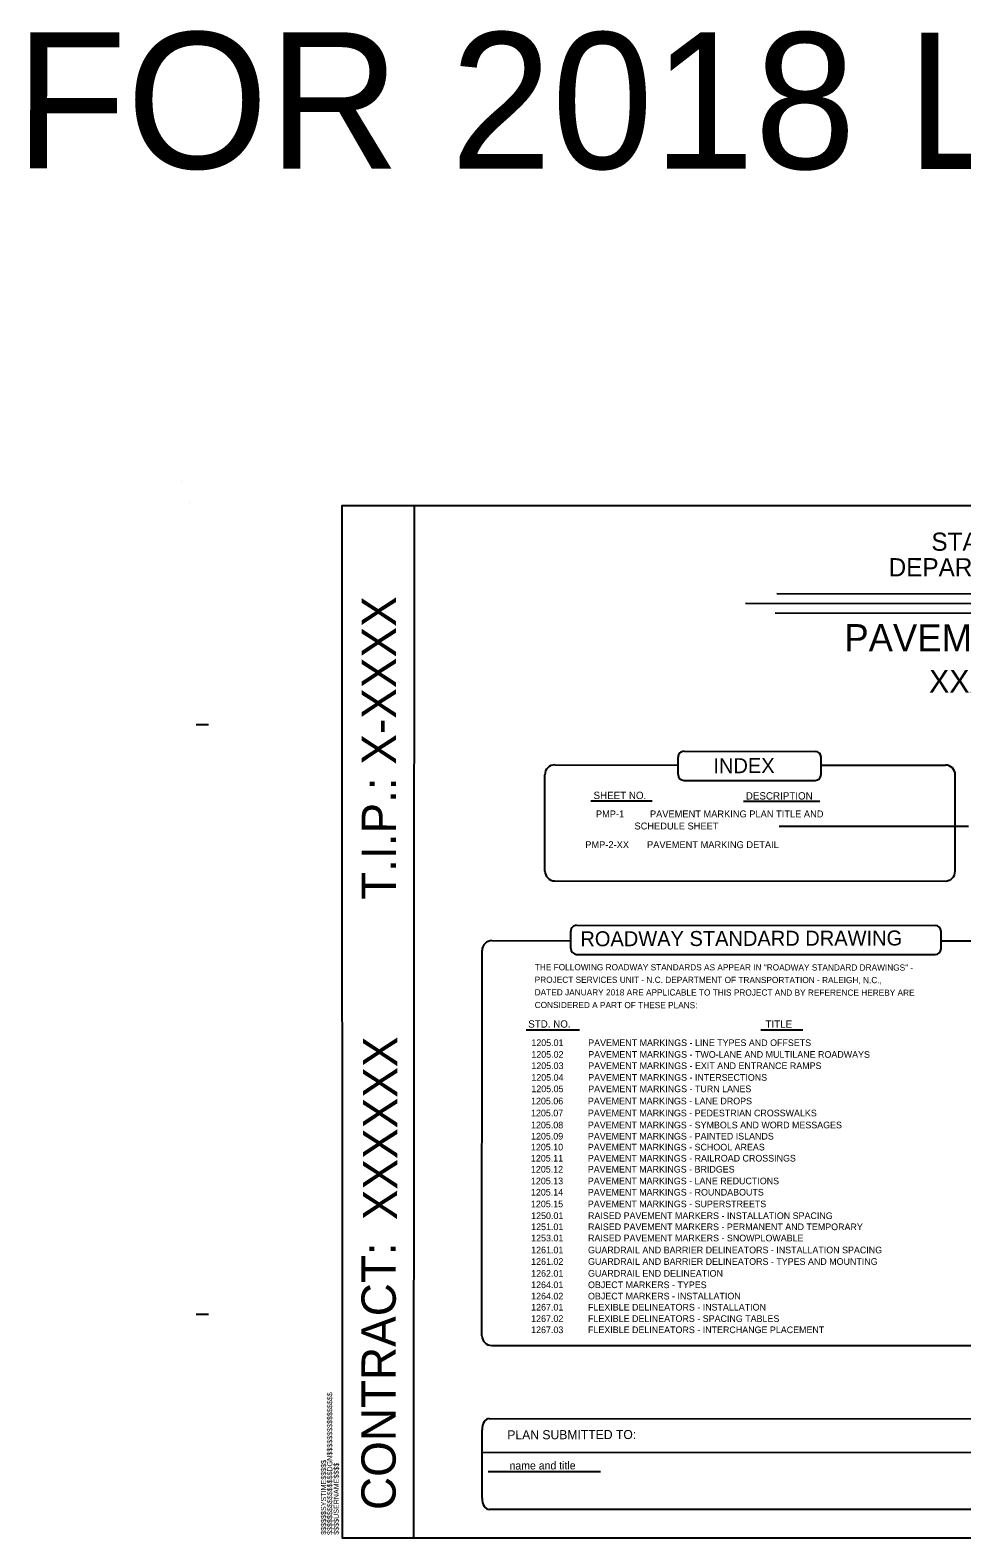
# Model space of a CAD drawing. Extents: x 2412958 to 2415566, y 564352 to 569392.
# Drawn here: x 2412958 to 2413907, y 567858 to 569392 of the extents above; entities that cross this region are included whole.
import ezdxf

# ---------------------------------------------------------------- set-up
doc = ezdxf.new("R2010")
doc.units = 0
for name, color, linetype in [('Default', 7, 'Continuous'), ('DEV BORDER CELL', 7, 'Continuous'), ('DEV TITLE SHEET CELL', 7, 'Continuous'), ('Old_Level_41', 7, 'Continuous'), ('Sheet Title CELL', 7, 'Continuous')]:
    doc.layers.add(name, color=color, linetype=linetype)

msp = doc.modelspace()

# ---------------------------------------------------------------- linework, layer by layer
at = {"layer": 'Default'}
for p, q in [((2413720.6, 568581.9), (2413913.3, 568581.9)), ((2413425.3, 567979.1), (2414032.2, 567979.2)), ((2413418.1, 567898.3), (2413418.1, 567967.7)), ((2413418.1, 567944.8), (2413939.2, 567945)), ((2413424.5, 567925.4), (2413538.6, 567925.3)), ((2414032.3, 567886.9), (2413425.3, 567886.8))]:
    msp.add_line(p, q, dxfattribs=at)
for points in [[(2413718.3, 568818.8), (2414412.1, 568818.4)], [(2413686.3, 568809), (2414440.8, 568808.7)], [(2413716.6, 568799.3), (2414410.4, 568798.9)]]:
    msp.add_lwpolyline(points, dxfattribs=at)
for centre, major_axis, start_param, end_param in [((2413425.3, 567967.7), (0, 11.5), 0.000702, 1.571498), ((2413425.3, 567898.3), (0, -11.5), 4.713091, 6.283887)]:
    msp.add_ellipse(centre, major_axis=major_axis, ratio=0.62659, start_param=start_param, end_param=end_param, dxfattribs=at)
at = {"layer": 'DEV BORDER CELL'}
for p, q in [((2413112.6, 568933), (2413112.6, 568933)), ((2413120, 568911.9), (2413120, 568911.9))]:
    msp.add_line(p, q, dxfattribs=at)
at = {"layer": 'Old_Level_41'}
for p, q in [((2413127, 568685.4), (2413139.5, 568685.4)), ((2413127, 568085.4), (2413139.5, 568085.4))]:
    msp.add_line(p, q, dxfattribs=at)
at = {"layer": 'Sheet Title CELL'}
for p, q in [((2413617.7, 568634.6), (2413617.7, 568652.3)), ((2413763.2, 568634.6), (2413763.2, 568652.2)), ((2413482.1, 568536.4), (2413482.1, 568634.4)), ((2413492.1, 568644.4), (2413617.7, 568644.3)), ((2413763.2, 568644.2), (2413889.8, 568644.2)), ((2413899.7, 568536.2), (2413899.8, 568634.2)), ((2413528.8, 568608), (2413591.4, 568608)), ((2413684.4, 568607.4), (2413762.1, 568607.4)), ((2413492.1, 568526.4), (2413889.7, 568526.2)), ((2413428.2, 568465.6), (2413508.4, 568465.5)), ((2413508.4, 568457.6), (2413508.4, 568475.2)), ((2413885.3, 568457.4), (2413885.3, 568475)), ((2413885.3, 568465.4), (2413961.1, 568465.3)), ((2413418, 568063.6), (2413418.2, 568455.6)), ((2413463, 568374.9), (2413517.2, 568374.9)), ((2413702, 568374.9), (2413744.8, 568374.9)), ((2413428, 568053.6), (2413960.9, 568053.6))]:
    msp.add_line(p, q, dxfattribs=at)
msp.add_lwpolyline([(2414775.5, 568908), (2413275.5, 568907.9), (2413275.6, 567857.9), (2414775.6, 567858)], close=True, dxfattribs=at)
for points in [[(2413348.7, 567857.9), (2413349.2, 568907.9)], [(2413623.7, 568658.3), (2413757.2, 568658.2)], [(2413623.7, 568628.6), (2413757.2, 568628.6)], [(2413514.4, 568481.2), (2413879.3, 568481)], [(2413514.4, 568451.6), (2413879.3, 568451.4)]]:
    msp.add_lwpolyline(points, dxfattribs=at)
for centre, radius, start, end in [((2413623.7, 568652.3), 6, 89.9734, 179.9734), ((2413757.2, 568652.2), 6, 359.9734, 89.9734), ((2413492.1, 568634.4), 10, 89.9734, 179.9734), ((2413623.7, 568634.6), 6, 179.9734, 269.9734), ((2413757.2, 568634.6), 6, 269.9734, 359.9734), ((2413889.8, 568634.2), 10, 359.9734, 89.9734), ((2413492.1, 568536.4), 10, 179.9734, 269.9734), ((2413889.7, 568536.2), 10, 269.9734, 359.9734), ((2413514.4, 568475.2), 6, 89.9734, 179.9734), ((2413879.3, 568475), 6, 359.9734, 89.9734), ((2413428.2, 568455.6), 10, 89.9734, 179.9734), ((2413514.4, 568457.6), 6, 179.9734, 269.9734), ((2413879.3, 568457.4), 6, 269.9734, 359.9734), ((2413428, 568063.6), 10, 179.9734, 269.9734)]:
    msp.add_arc(centre, radius, start, end, dxfattribs=at)

# ---------------------------------------------------------------- texts
at = {"layer": 'Default'}
for s, height, rotation, p in [('FOR 2018 LET PROJECTS', 138.702, 359.9734, (2412942.9, 569251.3)), ('STATE OF NORTH CAROLINA', 18.494, 359.9734, (2413875.5, 568862.3)), ('DEPARTMENT OF TRANSPORTATION', 18.494, 359.9734, (2413832, 568836.3)), ('T.I.P.: X-XXXX', 34.925, 89.9734, (2413330.5, 568507.1)), ('PAVEMENT MARKING PLAN', 27.74, 359.9734, (2413786.9, 568759.9)), ('XXXXXXXXXX COUNTY', 23.116, 359.9734, (2413873.1, 568718)), ('INDEX', 15.26, 0.1557, (2413653.6, 568635.9)), ('SHEET NO.', 7.45, 359.9734, (2413531.6, 568609.7)), ('DESCRIPTION', 7.45, 359.9734, (2413686.6, 568609.2)), ('PMP-1          PAVEMENT MARKING PLAN TITLE AND', 7.053, 360, (2413534, 568591)), ('               SCHEDULE SHEET', 7.053, 360, (2413534, 568578.7)), ('   PMP-2-XX       PAVEMENT MARKING DETAIL', 7.053, 360, (2413515.3, 568559.7)), ('ROADWAY STANDARD DRAWING', 15.257, 0.1557, (2413518.2, 568459.8)), ('STD. NO.', 7.45, 359.9734, (2413465.1, 568377.1)), ('TITLE', 7.45, 359.9734, (2413706.7, 568377)), ('XXXXXX', 34.92, 89.9734, (2413331.7, 568181.1)), ('1205.01          PAVEMENT MARKINGS - LINE TYPES AND OFFSETS', 6.771, 360, (2413468.3, 568358.3)), ('1205.02          PAVEMENT MARKINGS - TWO-LANE AND MULTILANE ROADWAYS', 6.771, 360, (2413468.3, 568346.4)), ('1205.03          PAVEMENT MARKINGS - EXIT AND ENTRANCE RAMPS', 6.771, 360, (2413468.3, 568334.9)), ('1205.04          PAVEMENT MARKINGS - INTERSECTIONS', 6.771, 360, (2413468.3, 568323)), ('1205.05          PAVEMENT MARKINGS - TURN LANES', 6.771, 360, (2413468.3, 568311.4)), ('1205.06          PAVEMENT MARKINGS - LANE DROPS', 6.771, 360, (2413468, 568299)), ('1205.07          PAVEMENT MARKINGS - PEDESTRIAN CROSSWALKS', 6.771, 360, (2413468, 568286.8)), ('1205.08          PAVEMENT MARKINGS - SYMBOLS AND WORD MESSAGES', 6.771, 360, (2413468, 568274.6)), ('1205.09          PAVEMENT MARKINGS - PAINTED ISLANDS', 6.771, 360, (2413468, 568263.2)), ('1205.10          PAVEMENT MARKINGS - SCHOOL AREAS', 6.771, 360, (2413467.9, 568252.1)), ('1205.11          PAVEMENT MARKINGS - RAILROAD CROSSINGS', 6.771, 360, (2413467.9, 568240.8)), ('1205.12          PAVEMENT MARKINGS - BRIDGES', 6.771, 360, (2413467.9, 568229.6)), ('1205.13          PAVEMENT MARKINGS - LANE REDUCTIONS', 6.771, 360, (2413467.9, 568217.7)), ('1205.14          PAVEMENT MARKINGS - ROUNDABOUTS', 6.771, 360, (2413467.9, 568206.2)), ('1205.15          PAVEMENT MARKINGS - SUPERSTREETS', 6.771, 360, (2413467.9, 568194.3)), ('1250.01          RAISED PAVEMENT MARKERS - INSTALLATION SPACING', 6.771, 360, (2413468.1, 568182.3)), ('1251.01          RAISED PAVEMENT MARKERS - PERMANENT AND TEMPORARY', 6.771, 360, (2413468.1, 568171)), ('CONTRACT:', 34.92, 89.9734, (2413330.2, 567886.2)), ('1253.01          RAISED PAVEMENT MARKERS - SNOWPLOWABLE', 6.771, 360, (2413468.1, 568159.6)), ('1261.01          GUARDRAIL AND BARRIER DELINEATORS - INSTALLATION SPACING', 6.771, 360, (2413468.1, 568147.4)), ('1261.02          GUARDRAIL AND BARRIER DELINEATORS - TYPES AND MOUNTING', 6.771, 360, (2413468.1, 568135.7)), ('1262.01          GUARDRAIL END DELINEATION', 6.771, 360, (2413468.1, 568123.6)), ('1264.01          OBJECT MARKERS - TYPES', 6.771, 360, (2413468.1, 568112)), ('1264.02          OBJECT MARKERS - INSTALLATION', 6.771, 360, (2413468.1, 568100.5)), ('1267.01          FLEXIBLE DELINEATORS - INSTALLATION', 6.771, 360, (2413468.1, 568089.2)), ('1267.02          FLEXIBLE DELINEATORS - SPACING TABLES', 6.771, 360, (2413468.1, 568077.6)), ('1267.03          FLEXIBLE DELINEATORS - INTERCHANGE PLACEMENT', 6.771, 360, (2413468.1, 568066.2)), ('PLAN SUBMITTED TO:', 9.247, 0.1557, (2413443.8, 567958.1)), ('name and title', 8, 0.1557, (2413446.1, 567927.4))]:
    msp.add_text(s, height=height, rotation=rotation, dxfattribs=at).set_placement(p)
at = {"layer": 'DEV TITLE SHEET CELL'}
for s, p in [('THE FOLLOWING ROADWAY STANDARDS AS APPEAR IN "ROADWAY STANDARD DRAWINGS" -', (2413471.8, 568435.5)), ('PROJECT SERVICES UNIT - N.C. DEPARTMENT OF TRANSPORTATION - RALEIGH, N.C.,', (2413471.7, 568422.7)), ('DATED JANUARY 2018 ARE APPLICABLE TO THIS PROJECT AND BY REFERENCE HEREBY ARE ', (2413471.7, 568409.9)), ('CONSIDERED A PART OF THESE PLANS:', (2413471.7, 568397))]:
    msp.add_text(s, height=6.3, rotation=359.9332, dxfattribs=at).set_placement(p)
at = {"layer": 'Old_Level_41'}
for s, p in [('$$$$$$$$$$$$$$$$DGN$$$$$$$$$$$$$$$$', (2413265.7, 567860.9)), ('$$$$$$SYSTIME$$$$$', (2413259.4, 567861)), ('$$$$USERNAME$$$$', (2413272.3, 567861))]:
    msp.add_text(s, height=5.25, rotation=90.0042, dxfattribs=at).set_placement(p)

doc.saveas('drawing.dxf')
